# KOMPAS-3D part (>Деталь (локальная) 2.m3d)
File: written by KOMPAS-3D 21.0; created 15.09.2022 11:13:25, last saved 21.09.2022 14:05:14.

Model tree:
1. Операция без истории:1
2. Развертка  (labels: Сталь 45  ГОСТ 1050-2013)

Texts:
  Толщина листового тела
  Глубина освобождения сгиба
  Ширина освобождения сгиба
